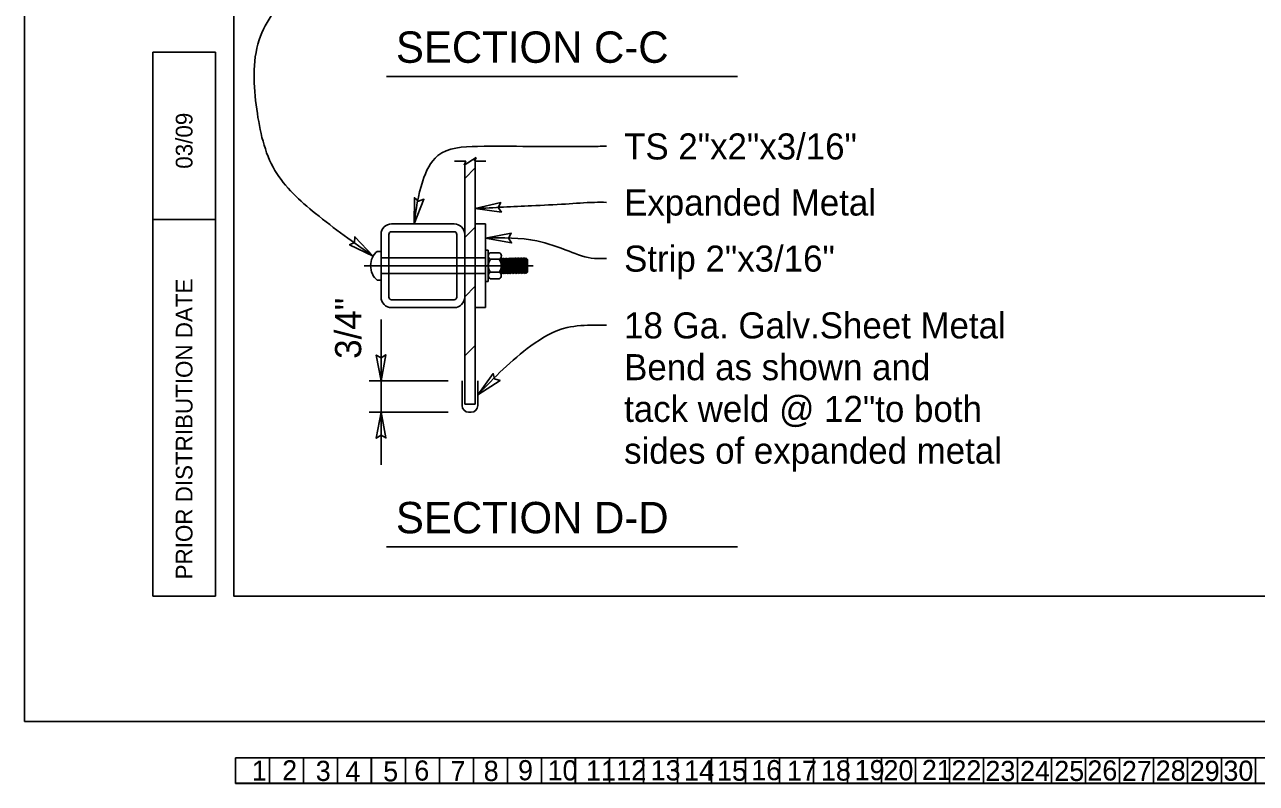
# Model space of a CAD drawing. Extents: x 0 to 2.83, y -0.03 to 1.83.
# Drawn here: x 0 to 0.613, y -0.031 to 0.347 of the extents above; entities that cross this region are included whole.
import ezdxf

# ---------------------------------------------------------------- set-up
doc = ezdxf.new("R2010")
doc.units = 0
for name, color, linetype in [('1', 7, 'Continuous'), ('10', 7, 'Continuous'), ('11', 7, 'Continuous'), ('12', 7, 'Continuous'), ('13', 7, 'Continuous'), ('14', 7, 'Continuous'), ('15', 7, 'Continuous'), ('16', 7, 'Continuous'), ('17', 7, 'Continuous'), ('18', 7, 'Continuous'), ('19', 7, 'Continuous'), ('2', 7, 'Continuous'), ('20', 7, 'Continuous'), ('21', 7, 'Continuous'), ('22', 7, 'Continuous'), ('23', 7, 'Continuous'), ('24', 7, 'Continuous'), ('25', 7, 'Continuous'), ('26', 7, 'Continuous'), ('27', 7, 'Continuous'), ('28', 7, 'Continuous'), ('29', 7, 'Continuous'), ('3', 7, 'Continuous'), ('30', 7, 'Continuous'), ('4', 7, 'Continuous'), ('5', 7, 'Continuous'), ('50', 7, 'Continuous'), ('52', 7, 'Continuous'), ('54', 7, 'Continuous'), ('55', 7, 'Continuous'), ('57', 7, 'Continuous'), ('6', 7, 'Continuous'), ('62', 7, 'Continuous'), ('63', 7, 'Continuous'), ('7', 7, 'Continuous'), ('8', 7, 'Continuous'), ('9', 7, 'Continuous')]:
    doc.layers.add(name, color=color, linetype=linetype)

msp = doc.modelspace()

# ---------------------------------------------------------------- linework, layer by layer
at = {"layer": '50'}
for p, q in [((0.21918, 0.27045), (0.22439, 0.27566)), ((0.21918, 0.24099), (0.22439, 0.2462)), ((0.21918, 0.21153), (0.22439, 0.21674)), ((0.21918, 0.18206), (0.22439, 0.18727)), ((0, 0), (0, 0))]:
    msp.add_line(p, q, dxfattribs=at)
at = {"layer": '52'}
for p, q in [((0.21918, 0.27734), (0.21918, 0.15799)), ((0.22439, 0.27903), (0.22439, 0.15799)), ((0.18272, 0.2478), (0.21397, 0.2478)), ((0.22439, 0.2478), (0.22959, 0.2478)), ((0.22959, 0.2478), (0.22959, 0.20613)), ((0.17751, 0.24259), (0.17751, 0.21134)), ((0.18142, 0.24259), (0.18142, 0.21134)), ((0.18272, 0.24389), (0.21397, 0.24389)), ((0.21527, 0.24259), (0.21527, 0.21134)), ((0.17562, 0.23413), (0.17751, 0.23413)), ((0.17751, 0.2198), (0.17751, 0.23413)), ((0.22959, 0.23478), (0.22959, 0.21915)), ((0.2309, 0.23478), (0.22959, 0.23478)), ((0.2309, 0.23478), (0.2309, 0.21915)), ((0.232, 0.23347), (0.23632, 0.23347)), ((0.17751, 0.23087), (0.22959, 0.23087)), ((0.22959, 0.22632), (0.2309, 0.22762)), ((0.2309, 0.2319), (0.2309, 0.22209)), ((0.2309, 0.23004), (0.2309, 0.2249)), ((0.232, 0.23022), (0.23632, 0.23022)), ((0.23741, 0.23164), (0.23741, 0.22193)), ((0.23764, 0.23081), (0.23741, 0.23057)), ((0.23816, 0.22336), (0.23741, 0.2296)), ((0.23857, 0.223), (0.23764, 0.23081)), ((0.23805, 0.23044), (0.23764, 0.23081)), ((0.23839, 0.23081), (0.23805, 0.23044)), ((0.23891, 0.22336), (0.23805, 0.23044)), ((0.23879, 0.23046), (0.23838, 0.23082)), ((0.23932, 0.22301), (0.23839, 0.23081)), ((0.23913, 0.23082), (0.23879, 0.23046)), ((0.23966, 0.22337), (0.2388, 0.23047)), ((0.24007, 0.22301), (0.23913, 0.23082)), ((0.23954, 0.23046), (0.23913, 0.23082)), ((0.23989, 0.23082), (0.23954, 0.23046)), ((0.2404, 0.22337), (0.23954, 0.23046)), ((0.24029, 0.23047), (0.23988, 0.23083)), ((0.24081, 0.22302), (0.23989, 0.23082)), ((0.24063, 0.23083), (0.24029, 0.23047)), ((0.24116, 0.22339), (0.2403, 0.23048)), ((0.24157, 0.22302), (0.24063, 0.23083)), ((0.24104, 0.23047), (0.24063, 0.23083)), ((0.24139, 0.23083), (0.24104, 0.23047)), ((0.2419, 0.22339), (0.24104, 0.23047)), ((0.24178, 0.23048), (0.24137, 0.23084)), ((0.24231, 0.22303), (0.24139, 0.23083)), ((0.24213, 0.23084), (0.24178, 0.23048)), ((0.24265, 0.2234), (0.24179, 0.23049)), ((0.24307, 0.22303), (0.24213, 0.23084)), ((0.24254, 0.23048), (0.24213, 0.23084)), ((0.24288, 0.23084), (0.24254, 0.23048)), ((0.2434, 0.2234), (0.24254, 0.23048)), ((0.24328, 0.23049), (0.24287, 0.23086)), ((0.24381, 0.22304), (0.24288, 0.23084)), ((0.24362, 0.23086), (0.24328, 0.23049)), ((0.24415, 0.22341), (0.24329, 0.2305)), ((0.24456, 0.22304), (0.24362, 0.23086)), ((0.24404, 0.23049), (0.24362, 0.23086)), ((0.24438, 0.23086), (0.24404, 0.23049)), ((0.24489, 0.22341), (0.24404, 0.23049)), ((0.24478, 0.2305), (0.24437, 0.23087)), ((0.2453, 0.22305), (0.24438, 0.23086)), ((0.24512, 0.23087), (0.24478, 0.2305)), ((0.24565, 0.22342), (0.24479, 0.23051)), ((0.24606, 0.22305), (0.24512, 0.23087)), ((0.24553, 0.2305), (0.24512, 0.23087)), ((0.24588, 0.23087), (0.24553, 0.2305)), ((0.24639, 0.22342), (0.24553, 0.2305)), ((0.24628, 0.23051), (0.24586, 0.23088)), ((0.2468, 0.22307), (0.24588, 0.23087)), ((0.24662, 0.23088), (0.24628, 0.23051)), ((0.24714, 0.22343), (0.24629, 0.23052)), ((0.24756, 0.22307), (0.24662, 0.23088)), ((0.24703, 0.23051), (0.24662, 0.23088)), ((0.24737, 0.23088), (0.24703, 0.23051)), ((0.24789, 0.22343), (0.24703, 0.23051)), ((0.24831, 0.22307), (0.24737, 0.23088)), ((0.24779, 0.23051), (0.24737, 0.23088)), ((0.24812, 0.23088), (0.24779, 0.23051)), ((0.24863, 0.22343), (0.24779, 0.23051)), ((0.24907, 0.22307), (0.24812, 0.23088)), ((0.24854, 0.23051), (0.24812, 0.23088)), ((0.24886, 0.23088), (0.24854, 0.23051)), ((0.24939, 0.22343), (0.24854, 0.23051)), ((0.24981, 0.22307), (0.24886, 0.23088)), ((0.2493, 0.23051), (0.24886, 0.23088)), ((0.24963, 0.23088), (0.2493, 0.23051)), ((0.25013, 0.22343), (0.2493, 0.23051)), ((0.24996, 0.228), (0.24963, 0.23088)), ((0.25043, 0.23015), (0.24963, 0.23088)), ((0.25004, 0.23049), (0.25004, 0.23049)), ((0.25013, 0.22343), (0.25013, 0.23042)), ((0.25043, 0.22376), (0.25043, 0.23015)), ((0.17751, 0.22305), (0.22959, 0.22305)), ((0.232, 0.22371), (0.23632, 0.22371)), ((0.23782, 0.223), (0.23741, 0.22647)), ((0.23741, 0.22335), (0.23782, 0.223)), ((0.23782, 0.223), (0.23816, 0.22336)), ((0.23816, 0.22336), (0.23857, 0.223)), ((0.23857, 0.223), (0.23891, 0.22336)), ((0.23897, 0.22331), (0.23932, 0.22301)), ((0.23932, 0.22301), (0.23966, 0.22337)), ((0.23966, 0.22337), (0.24007, 0.22301)), ((0.24007, 0.22301), (0.2404, 0.22337)), ((0.24046, 0.22332), (0.24081, 0.22302)), ((0.24081, 0.22302), (0.24116, 0.22339)), ((0.24116, 0.22339), (0.24157, 0.22302)), ((0.24157, 0.22302), (0.2419, 0.22339)), ((0.24196, 0.22333), (0.24231, 0.22303)), ((0.24231, 0.22303), (0.24265, 0.2234)), ((0.24265, 0.2234), (0.24307, 0.22303)), ((0.24307, 0.22303), (0.2434, 0.2234)), ((0.24346, 0.22334), (0.24381, 0.22304)), ((0.24381, 0.22304), (0.24415, 0.22341)), ((0.24415, 0.22341), (0.24456, 0.22304)), ((0.24456, 0.22304), (0.24489, 0.22341)), ((0.24496, 0.22336), (0.2453, 0.22305)), ((0.2453, 0.22305), (0.24565, 0.22342)), ((0.24565, 0.22342), (0.24606, 0.22305)), ((0.24606, 0.22305), (0.24639, 0.22342)), ((0.24645, 0.22337), (0.2468, 0.22307)), ((0.2468, 0.22307), (0.24714, 0.22343)), ((0.24714, 0.22343), (0.24756, 0.22307)), ((0.24756, 0.22307), (0.24789, 0.22343)), ((0.24789, 0.22343), (0.24831, 0.22307)), ((0.24831, 0.22307), (0.24863, 0.22343)), ((0.24863, 0.22343), (0.24907, 0.22307)), ((0.24907, 0.22307), (0.24939, 0.22343)), ((0.24939, 0.22343), (0.24981, 0.22307)), ((0.24981, 0.22307), (0.25043, 0.22376)), ((0.17562, 0.2198), (0.17751, 0.2198)), ((0.2309, 0.21915), (0.22959, 0.21915)), ((0.232, 0.22046), (0.23632, 0.22046)), ((0.18272, 0.21004), (0.21397, 0.21004)), ((0.18272, 0.20613), (0.21397, 0.20613)), ((0.22439, 0.20613), (0.22959, 0.20613)), ((0.21788, 0.16967), (0.21788, 0.1573)), ((0.22569, 0.16967), (0.22569, 0.1573)), ((0.21918, 0.15799), (0.22439, 0.15799)), ((0.22113, 0.15405), (0.22243, 0.15405))]:
    msp.add_line(p, q, dxfattribs=at)
for centre, radius, start, end in [((0.18272, 0.24259), 0.00521, 90, 180), ((0.21397, 0.24259), 0.00521, 0, 90), ((0.18272, 0.24259), 0.0013, 90, 180), ((0.21397, 0.24259), 0.0013, 0, 90), ((0.18272, 0.21134), 0.00521, 180, 270), ((0.18272, 0.21134), 0.0013, 180, 270), ((0.21397, 0.21134), 0.0013, 270, 0), ((0.21397, 0.21134), 0.00521, 270, 0), ((0.22113, 0.1573), 0.00326, 180, 270), ((0.22243, 0.1573), 0.00326, 270, 0)]:
    msp.add_arc(centre, radius, start, end, dxfattribs=at)
for centre, major_axis, ratio, start_param, end_param in [((0.17968, 0.22697), (0, -0.00858), 0.859504, 3.724506, 5.700272), ((0.23256, 0.23184), (0, -0.00173), 0.961595, 3.48319, 5.941588), ((0.23576, 0.23184), (0, 0.00173), 0.961595, 3.48319, 5.941588), ((0.23588, 0.22696), (0, -0.00518), 0.961595, 4.033857, 5.390921), ((0.23244, 0.22696), (0, 0.00518), 0.961595, 4.033857, 5.390921), ((0.23255, 0.22209), (0, -0.00172), 0.961595, 3.483095, 5.941683), ((0.23576, 0.22209), (0, 0.00172), 0.961595, 3.483095, 5.941683)]:
    msp.add_ellipse(centre, major_axis=major_axis, ratio=ratio, start_param=start_param, end_param=end_param, dxfattribs=at)
at = {"layer": '54'}
for points in [[(0.19396, 0.2478), (0.19885, 0.26007), (0.19622, 0.25906), (0.19414, 0.26086)], [(0.22439, 0.25541), (0.23748, 0.25371), (0.23585, 0.256), (0.23709, 0.25847)], [(0.17356, 0.23177), (0.16453, 0.2414), (0.16433, 0.23859), (0.16181, 0.23747)], [(0.22953, 0.24078), (0.24252, 0.23836), (0.24102, 0.24074), (0.24238, 0.24314)], [(0.17751, 0.16967), (0.17989, 0.18267), (0.17751, 0.18116), (0.17511, 0.18252)], [(0.22569, 0.16274), (0.23679, 0.1699), (0.23406, 0.1706), (0.23341, 0.17328)], [(0.17751, 0.15405), (0.17514, 0.14106), (0.17751, 0.14257), (0.17991, 0.14121)]]:
    msp.add_lwpolyline(points, close=True, dxfattribs=at)
at = {"layer": '55'}
for p, q in [((0.21981, 0.27903), (0.21408, 0.27903)), ((0.22495, 0.28092), (0.21886, 0.27714)), ((0.21886, 0.27714), (0.21981, 0.27903)), ((0.22495, 0.28092), (0.224, 0.27903)), ((0.22973, 0.27903), (0.224, 0.27903)), ((0.16917, 0.22697), (0.25329, 0.22697)), ((0.17751, 0.20018), (0.17751, 0.16967)), ((0.17165, 0.16967), (0.21092, 0.16967)), ((0.17751, 0.16967), (0.17751, 0.15405)), ((0.17165, 0.15405), (0.21092, 0.15405)), ((0.17751, 0.15405), (0.17751, 0.12789))]:
    msp.add_line(p, q, dxfattribs=at)
for points in [[(0.28975, 0.43006), (0.27864, 0.43002), (0.26423, 0.42097), (0.25353, 0.40368), (0.23089, 0.38268), (0.1959, 0.37239), (0.16379, 0.37074), (0.13497, 0.36333), (0.11686, 0.33946), (0.11562, 0.30488), (0.12468, 0.27441), (0.14485, 0.25301), (0.17356, 0.23177)], [(0.28975, 0.28647), (0.28147, 0.2864), (0.25134, 0.2864), (0.22552, 0.2864), (0.20572, 0.28181), (0.19826, 0.26919), (0.19396, 0.2478)], [(0.28975, 0.25855), (0.28382, 0.25855), (0.26942, 0.25771), (0.25249, 0.25685), (0.22439, 0.25541)], [(0.28975, 0.23062), (0.28382, 0.23062), (0.27114, 0.23418), (0.25507, 0.23935), (0.22953, 0.24078)], [(0.28975, 0.19736), (0.28382, 0.19736), (0.27019, 0.19618), (0.25219, 0.1871), (0.22569, 0.16274)]]:
    msp.add_spline(points, degree=3, dxfattribs=at)
at = {"layer": '57'}
for p, q in [((0.18018, 0.32128), (0.35508, 0.32128)), ((0.18018, 0.08699), (0.35508, 0.08699))]:
    msp.add_line(p, q, dxfattribs=at)
at = {"layer": '62'}
for p, q in [((0.10494, -0.01804), (1.17174, -0.01804)), ((0.10494, -0.01804), (0.10494, -0.03074)), ((0.10496, -0.0181), (1.17175, -0.0181)), ((0.10496, -0.0181), (0.10496, -0.0308)), ((0.12188, -0.01804), (0.12188, -0.03074)), ((0.12189, -0.0181), (0.12189, -0.0308)), ((0.13881, -0.01804), (0.13881, -0.03074)), ((0.13882, -0.0181), (0.13882, -0.0308)), ((0.15574, -0.01804), (0.15574, -0.03074)), ((0.15576, -0.0181), (0.15576, -0.0308)), ((0.17267, -0.01804), (0.17267, -0.03074)), ((0.17269, -0.0181), (0.17269, -0.0308)), ((0.18961, -0.01804), (0.18961, -0.03074)), ((0.18962, -0.0181), (0.18962, -0.0308)), ((0.20654, -0.01804), (0.20654, -0.03074)), ((0.20656, -0.0181), (0.20656, -0.0308)), ((0.22348, -0.01804), (0.22348, -0.03074)), ((0.22349, -0.0181), (0.22349, -0.0308)), ((0.24041, -0.01804), (0.24041, -0.03074)), ((0.24042, -0.0181), (0.24042, -0.0308)), ((0.25734, -0.01804), (0.25734, -0.03074)), ((0.25736, -0.0181), (0.25736, -0.0308)), ((0.27427, -0.01804), (0.27427, -0.03074)), ((0.27429, -0.0181), (0.27429, -0.0308)), ((0.29121, -0.01804), (0.29121, -0.03074)), ((0.29122, -0.0181), (0.29122, -0.0308)), ((0.30814, -0.01804), (0.30814, -0.03074)), ((0.30816, -0.0181), (0.30816, -0.0308)), ((0.32508, -0.01804), (0.32508, -0.03074)), ((0.32509, -0.0181), (0.32509, -0.0308)), ((0.34201, -0.01804), (0.34201, -0.03074)), ((0.34202, -0.0181), (0.34202, -0.0308)), ((0.35894, -0.01804), (0.35894, -0.03074)), ((0.35896, -0.0181), (0.35896, -0.0308)), ((0.37588, -0.01804), (0.37588, -0.03074)), ((0.37589, -0.0181), (0.37589, -0.0308)), ((0.39281, -0.01804), (0.39281, -0.03074)), ((0.39282, -0.0181), (0.39282, -0.0308)), ((0.40974, -0.01804), (0.40974, -0.03074)), ((0.40976, -0.0181), (0.40976, -0.0308)), ((0.42668, -0.01804), (0.42668, -0.03074)), ((0.42669, -0.0181), (0.42669, -0.0308)), ((0.44361, -0.01804), (0.44361, -0.03074)), ((0.44362, -0.0181), (0.44362, -0.0308)), ((0.46054, -0.01804), (0.46054, -0.03074)), ((0.46056, -0.0181), (0.46056, -0.0308)), ((0.47748, -0.01804), (0.47748, -0.03074)), ((0.47749, -0.0181), (0.47749, -0.0308)), ((0.49441, -0.01804), (0.49441, -0.03074)), ((0.49442, -0.0181), (0.49442, -0.0308)), ((0.51134, -0.01804), (0.51134, -0.03074)), ((0.51136, -0.0181), (0.51136, -0.0308)), ((0.52828, -0.01804), (0.52828, -0.03074)), ((0.52829, -0.0181), (0.52829, -0.0308)), ((0.54521, -0.01804), (0.54521, -0.03074)), ((0.54522, -0.0181), (0.54522, -0.0308)), ((0.56214, -0.01804), (0.56214, -0.03074)), ((0.56216, -0.0181), (0.56216, -0.0308)), ((0.57908, -0.01804), (0.57908, -0.03074)), ((0.57909, -0.0181), (0.57909, -0.0308)), ((0.59601, -0.01804), (0.59601, -0.03074)), ((0.59602, -0.0181), (0.59602, -0.0308)), ((0.61294, -0.01804), (0.61294, -0.03074)), ((0.61296, -0.0181), (0.61296, -0.0308)), ((0.10494, -0.03074), (1.17174, -0.03074)), ((0.10496, -0.0308), (1.17175, -0.0308))]:
    msp.add_line(p, q, dxfattribs=at)
at = {"layer": '63'}
for p, q in [((0, 0), (0, 1.83333)), ((0.06381, 0.06244), (0.06381, 0.33328)), ((0.09506, 0.33328), (0.06381, 0.33328)), ((0.09506, 0.06244), (0.09506, 0.33328)), ((0.09506, 0.24994), (0.06381, 0.24994)), ((0.09506, 0.06244), (0.06381, 0.06244)), ((2.83333, 0), (0, 0))]:
    msp.add_line(p, q, dxfattribs=at)
msp.add_lwpolyline([(2.72918, 1.77077), (0.10418, 1.77077), (0.10418, 0.06244), (2.72918, 0.06244)], close=True, dxfattribs=at)

# ---------------------------------------------------------------- texts
at = {"layer": '1'}
for p in [(0.11316, -0.02944), (0.11317, -0.02949)]:
    msp.add_text('1', height=0.01, rotation=360, dxfattribs=at).set_placement(p)
at = {"layer": '10'}
for p in [(0.26046, -0.02928), (0.26047, -0.02934)]:
    msp.add_text('10', height=0.01, rotation=360, dxfattribs=at).set_placement(p)
at = {"layer": '11'}
for p in [(0.2796, -0.02937), (0.27961, -0.02942)]:
    msp.add_text('11', height=0.01, rotation=360, dxfattribs=at).set_placement(p)
at = {"layer": '12'}
for p in [(0.29469, -0.02925), (0.29471, -0.0293)]:
    msp.add_text('12', height=0.01, rotation=360, dxfattribs=at).set_placement(p)
at = {"layer": '13'}
for p in [(0.31181, -0.02928), (0.31182, -0.02933)]:
    msp.add_text('13', height=0.01, rotation=360, dxfattribs=at).set_placement(p)
at = {"layer": '14'}
for p in [(0.32844, -0.02939), (0.32846, -0.02944)]:
    msp.add_text('14', height=0.01, rotation=360, dxfattribs=at).set_placement(p)
at = {"layer": '15'}
for p in [(0.34488, -0.02946), (0.34489, -0.02951)]:
    msp.add_text('15', height=0.01, rotation=360, dxfattribs=at).set_placement(p)
at = {"layer": '16'}
for p in [(0.3619, -0.02918), (0.36191, -0.02923)]:
    msp.add_text('16', height=0.01, rotation=360, dxfattribs=at).set_placement(p)
at = {"layer": '17'}
for p in [(0.3797, -0.02946), (0.37971, -0.02951)]:
    msp.add_text('17', height=0.01, rotation=360, dxfattribs=at).set_placement(p)
at = {"layer": '18'}
for p in [(0.39663, -0.02938), (0.39664, -0.02943)]:
    msp.add_text('18', height=0.01, rotation=360, dxfattribs=at).set_placement(p)
at = {"layer": '19'}
for p in [(0.4134, -0.02918), (0.41342, -0.02923)]:
    msp.add_text('19', height=0.01, rotation=360, dxfattribs=at).set_placement(p)
at = {"layer": '2'}
for p in [(0.12828, -0.02928), (0.12829, -0.02934)]:
    msp.add_text('2', height=0.01, rotation=360, dxfattribs=at).set_placement(p)
at = {"layer": '20'}
for p in [(0.42774, -0.02926), (0.42776, -0.02931)]:
    msp.add_text('20', height=0.01, rotation=360, dxfattribs=at).set_placement(p)
at = {"layer": '21'}
for p in [(0.44688, -0.02909), (0.44689, -0.02914)]:
    msp.add_text('21', height=0.01, rotation=360, dxfattribs=at).set_placement(p)
at = {"layer": '22'}
for p in [(0.46158, -0.02929), (0.46159, -0.02934)]:
    msp.add_text('22', height=0.01, rotation=360, dxfattribs=at).set_placement(p)
at = {"layer": '23'}
for p in [(0.47852, -0.02958), (0.47853, -0.02963)]:
    msp.add_text('23', height=0.01, rotation=360, dxfattribs=at).set_placement(p)
at = {"layer": '24'}
for p in [(0.49576, -0.02958), (0.49577, -0.02963)]:
    msp.add_text('24', height=0.01, rotation=360, dxfattribs=at).set_placement(p)
at = {"layer": '25'}
for p in [(0.51281, -0.02958), (0.51282, -0.02963)]:
    msp.add_text('25', height=0.01, rotation=360, dxfattribs=at).set_placement(p)
at = {"layer": '26'}
for p in [(0.52931, -0.02936), (0.52932, -0.02941)]:
    msp.add_text('26', height=0.01, rotation=360, dxfattribs=at).set_placement(p)
at = {"layer": '27'}
for p in [(0.54648, -0.02958), (0.54649, -0.02963)]:
    msp.add_text('27', height=0.01, rotation=360, dxfattribs=at).set_placement(p)
at = {"layer": '28'}
for p in [(0.56333, -0.02938), (0.56334, -0.02943)]:
    msp.add_text('28', height=0.01, rotation=360, dxfattribs=at).set_placement(p)
at = {"layer": '29'}
for p in [(0.58032, -0.02956), (0.58034, -0.02961)]:
    msp.add_text('29', height=0.01, rotation=360, dxfattribs=at).set_placement(p)
at = {"layer": '3'}
for p in [(0.145, -0.02955), (0.14501, -0.02961)]:
    msp.add_text('3', height=0.01, rotation=360, dxfattribs=at).set_placement(p)
at = {"layer": '30'}
for p in [(0.59706, -0.02946), (0.59707, -0.02951)]:
    msp.add_text('30', height=0.01, rotation=360, dxfattribs=at).set_placement(p)
at = {"layer": '4'}
for p in [(0.15973, -0.02984), (0.15975, -0.0299)]:
    msp.add_text('4', height=0.01, rotation=360, dxfattribs=at).set_placement(p)
at = {"layer": '5'}
for p in [(0.17858, -0.02977), (0.17859, -0.02982)]:
    msp.add_text('5', height=0.01, rotation=360, dxfattribs=at).set_placement(p)
at = {"layer": '57'}
for s, height, p in [('SECTION C-C', 0.015625, (0.18491, 0.32804)), ('TS 2"x2"x3/16"', 0.0129801, (0.29857, 0.27989)), ('Expanded Metal', 0.0129801, (0.29857, 0.25197)), ('Strip 2"x3/16"', 0.0129801, (0.29857, 0.22404)), ('18 Ga. Galv.Sheet Metal ', 0.0129801, (0.29857, 0.19078)), ('Bend as shown and', 0.0129801, (0.29857, 0.16998)), ('tack weld @ 12"to both', 0.0129801, (0.29857, 0.14919)), ('sides of expanded metal', 0.0129801, (0.29857, 0.1284)), ('SECTION D-D', 0.015625, (0.18491, 0.09374))]:
    msp.add_text(s, height=height, dxfattribs=at).set_placement(p)
msp.add_text('3/4"', height=0.013021, rotation=90, dxfattribs=at).set_placement((0.16762, 0.18062))
at = {"layer": '6'}
for p in [(0.19409, -0.02938), (0.19411, -0.02943)]:
    msp.add_text('6', height=0.01, rotation=360, dxfattribs=at).set_placement(p)
at = {"layer": '63'}
for s, height, p in [('03/09', 0.008333, (0.0836, 0.27529)), ('PRIOR DISTRIBUTION DATE', 0.0083333, (0.0836, 0.07078))]:
    msp.add_text(s, height=height, rotation=90, dxfattribs=at).set_placement(p)
at = {"layer": '7'}
for p in [(0.21211, -0.02964), (0.21212, -0.02969)]:
    msp.add_text('7', height=0.01, rotation=360, dxfattribs=at).set_placement(p)
at = {"layer": '8'}
for p in [(0.22865, -0.02958), (0.22866, -0.02963)]:
    msp.add_text('8', height=0.01, rotation=360, dxfattribs=at).set_placement(p)
at = {"layer": '9'}
for p in [(0.24573, -0.02921), (0.24574, -0.02926)]:
    msp.add_text('9', height=0.01, rotation=360, dxfattribs=at).set_placement(p)

doc.saveas('drawing.dxf')
